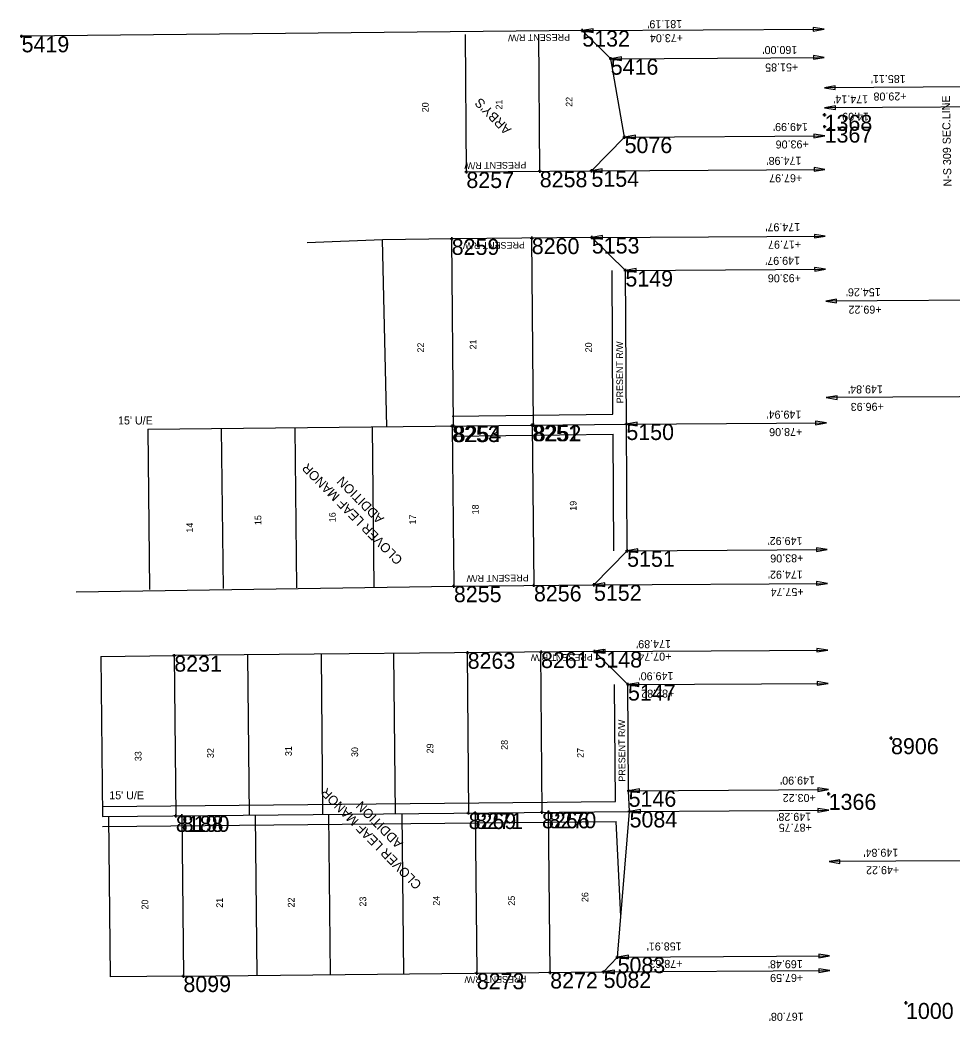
# Model space of a CAD drawing. Extents: x 2145146 to 2158053, y 137507 to 150829.
# Drawn here: x 2150207 to 2150906, y 144849 to 145599 of the extents above; entities that cross this region are included whole.
import ezdxf

# ---------------------------------------------------------------- set-up
doc = ezdxf.new("R2010")
doc.units = 0
for name, color, linetype in [('ALIGN_Cogo Points', 7, 'Continuous'), ('ALIGN_ROW Dimension', 7, 'Continuous'), ('ALIGN_ROW Line', 7, 'Continuous'), ('ALIGN_ROW Text', 7, 'Continuous'), ('PLSS_Block Line', 7, 'Continuous'), ('PLSS_Easement', 7, 'Continuous'), ('PLSS_Lot Line', 7, 'Continuous'), ('PLSS_Property Line', 7, 'Continuous'), ('PLSS_Text', 7, 'Continuous'), ('PLSS_Text_TURNED OFF', 7, 'Continuous')]:
    doc.layers.add(name, color=color, linetype=linetype)

# ---------------------------------------------------------------- blocks, each defined once
blk = doc.blocks.new('Arrowhd')
at = {"layer": 'PLSS_Property Line'}
blk.add_lwpolyline([(0.125, -0.021), (0.125, 0.021), (0, 0)], close=True, dxfattribs=at)

msp = doc.modelspace()

# ---------------------------------------------------------------- linework, layer by layer
at = {"layer": 'ALIGN_Cogo Points'}
for points in [[(2150207.75, 145586.84), (2150207.75, 145588.04), (2150207.75, 145586.84), (2150206.55, 145586.84), (2150207.75, 145586.84), (2150207.75, 145585.64), (2150207.75, 145586.84), (2150208.95, 145586.84)], [(2150627.9, 145591.12), (2150627.9, 145592.32), (2150627.9, 145591.12), (2150626.7, 145591.12), (2150627.9, 145591.12), (2150627.9, 145589.92), (2150627.9, 145591.12), (2150629.1, 145591.12)], [(2150649.21, 145570.05), (2150649.21, 145571.25), (2150649.21, 145570.05), (2150648.01, 145570.05), (2150649.21, 145570.05), (2150649.21, 145568.85), (2150649.21, 145570.05), (2150650.41, 145570.05)], [(2150809.47, 145528), (2150809.47, 145529.2), (2150809.47, 145528), (2150808.27, 145528), (2150809.47, 145528), (2150809.47, 145526.8), (2150809.47, 145528), (2150810.67, 145528)], [(2150809.52, 145519.17), (2150809.52, 145520.37), (2150809.52, 145519.17), (2150808.32, 145519.17), (2150809.52, 145519.17), (2150809.52, 145517.97), (2150809.52, 145519.17), (2150810.72, 145519.17)], [(2150659.58, 145511.33), (2150659.58, 145512.53), (2150659.58, 145511.33), (2150658.38, 145511.33), (2150659.58, 145511.33), (2150659.58, 145510.13), (2150659.58, 145511.33), (2150660.78, 145511.33)], [(2150541.04, 145485.16), (2150541.04, 145486.36), (2150541.04, 145485.16), (2150539.84, 145485.16), (2150541.04, 145485.16), (2150541.04, 145483.96), (2150541.04, 145485.16), (2150542.24, 145485.16)], [(2150596.04, 145485.7), (2150596.04, 145486.9), (2150596.04, 145485.7), (2150594.84, 145485.7), (2150596.04, 145485.7), (2150596.04, 145484.5), (2150596.04, 145485.7), (2150597.24, 145485.7)], [(2150634.74, 145486.08), (2150634.74, 145487.28), (2150634.74, 145486.08), (2150633.54, 145486.08), (2150634.74, 145486.08), (2150634.74, 145484.88), (2150634.74, 145486.08), (2150635.94, 145486.08)], [(2150530.05, 145435.05), (2150530.05, 145436.25), (2150530.05, 145435.05), (2150528.85, 145435.05), (2150530.05, 145435.05), (2150530.05, 145433.85), (2150530.05, 145435.05), (2150531.25, 145435.05)], [(2150590.05, 145435.64), (2150590.05, 145436.84), (2150590.05, 145435.64), (2150588.85, 145435.64), (2150590.05, 145435.64), (2150590.05, 145434.44), (2150590.05, 145435.64), (2150591.25, 145435.64)], [(2150635.05, 145436.08), (2150635.05, 145437.28), (2150635.05, 145436.08), (2150633.85, 145436.08), (2150635.05, 145436.08), (2150635.05, 145434.88), (2150635.05, 145436.08), (2150636.25, 145436.08)], [(2150660.2, 145411.33), (2150660.2, 145412.53), (2150660.2, 145411.33), (2150659, 145411.33), (2150660.2, 145411.33), (2150660.2, 145410.13), (2150660.2, 145411.33), (2150661.4, 145411.33)], [(2150530.37, 145294.83), (2150530.37, 145296.03), (2150530.37, 145294.83), (2150529.17, 145294.83), (2150530.37, 145294.83), (2150530.37, 145293.63), (2150530.37, 145294.83), (2150531.57, 145294.83)], [(2150531.45, 145294.84), (2150531.45, 145296.04), (2150531.45, 145294.84), (2150530.25, 145294.84), (2150531.45, 145294.84), (2150531.45, 145293.64), (2150531.45, 145294.84), (2150532.65, 145294.84)], [(2150590.37, 145295.41), (2150590.37, 145296.61), (2150590.37, 145295.41), (2150589.17, 145295.41), (2150590.37, 145295.41), (2150590.37, 145294.21), (2150590.37, 145295.41), (2150591.57, 145295.41)], [(2150591.45, 145295.42), (2150591.45, 145296.62), (2150591.45, 145295.42), (2150590.25, 145295.42), (2150591.45, 145295.42), (2150591.45, 145294.22), (2150591.45, 145295.42), (2150592.65, 145295.42)], [(2150660.92, 145296.33), (2150660.92, 145297.53), (2150660.92, 145296.33), (2150659.72, 145296.33), (2150660.92, 145296.33), (2150660.92, 145295.13), (2150660.92, 145296.33), (2150662.12, 145296.33)], [(2150661.51, 145201.33), (2150661.51, 145202.53), (2150661.51, 145201.33), (2150660.31, 145201.33), (2150661.51, 145201.33), (2150661.51, 145200.13), (2150661.51, 145201.33), (2150662.71, 145201.33)], [(2150531.67, 145174.83), (2150531.67, 145176.03), (2150531.67, 145174.83), (2150530.47, 145174.83), (2150531.67, 145174.83), (2150531.67, 145173.63), (2150531.67, 145174.83), (2150532.87, 145174.83)], [(2150591.67, 145175.42), (2150591.67, 145176.62), (2150591.67, 145175.42), (2150590.47, 145175.42), (2150591.67, 145175.42), (2150591.67, 145174.22), (2150591.67, 145175.42), (2150592.87, 145175.42)], [(2150636.66, 145175.86), (2150636.66, 145177.06), (2150636.66, 145175.86), (2150635.46, 145175.86), (2150636.66, 145175.86), (2150636.66, 145174.66), (2150636.66, 145175.86), (2150637.86, 145175.86)], [(2150322.13, 145122.78), (2150322.13, 145123.98), (2150322.13, 145122.78), (2150320.93, 145122.78), (2150322.13, 145122.78), (2150322.13, 145121.58), (2150322.13, 145122.78), (2150323.33, 145122.78)], [(2150541.99, 145124.93), (2150541.99, 145126.13), (2150541.99, 145124.93), (2150540.79, 145124.93), (2150541.99, 145124.93), (2150541.99, 145123.73), (2150541.99, 145124.93), (2150543.19, 145124.93)], [(2150596.99, 145125.47), (2150596.99, 145126.67), (2150596.99, 145125.47), (2150595.79, 145125.47), (2150596.99, 145125.47), (2150596.99, 145124.27), (2150596.99, 145125.47), (2150598.19, 145125.47)], [(2150636.99, 145125.86), (2150636.99, 145127.06), (2150636.99, 145125.86), (2150635.79, 145125.86), (2150636.99, 145125.86), (2150636.99, 145124.66), (2150636.99, 145125.86), (2150638.19, 145125.86)], [(2150662.13, 145101.09), (2150662.13, 145102.29), (2150662.13, 145101.09), (2150660.93, 145101.09), (2150662.13, 145101.09), (2150662.13, 145099.89), (2150662.13, 145101.09), (2150663.33, 145101.09)], [(2150859.27, 145060.92), (2150859.27, 145062.12), (2150859.27, 145060.92), (2150858.07, 145060.92), (2150859.27, 145060.92), (2150859.27, 145059.72), (2150859.27, 145060.92), (2150860.47, 145060.92)], [(2150662.61, 145021.5), (2150662.61, 145022.7), (2150662.61, 145021.5), (2150661.41, 145021.5), (2150662.61, 145021.5), (2150662.61, 145020.3), (2150662.61, 145021.5), (2150663.81, 145021.5)], [(2150812.52, 145019.18), (2150812.52, 145020.38), (2150812.52, 145019.18), (2150811.32, 145019.18), (2150812.52, 145019.18), (2150812.52, 145017.98), (2150812.52, 145019.18), (2150813.72, 145019.18)], [(2150323.31, 145002.7), (2150323.31, 145003.9), (2150323.31, 145002.7), (2150322.11, 145002.7), (2150323.31, 145002.7), (2150323.31, 145001.5), (2150323.31, 145002.7), (2150324.51, 145002.7)], [(2150327.82, 145002.74), (2150327.82, 145003.94), (2150327.82, 145002.74), (2150326.62, 145002.74), (2150327.82, 145002.74), (2150327.82, 145001.54), (2150327.82, 145002.74), (2150329.02, 145002.74)], [(2150542.69, 145004.85), (2150542.69, 145006.05), (2150542.69, 145004.85), (2150541.49, 145004.85), (2150542.69, 145004.85), (2150542.69, 145003.65), (2150542.69, 145004.85), (2150543.89, 145004.85)], [(2150547.69, 145004.9), (2150547.69, 145006.1), (2150547.69, 145004.9), (2150546.49, 145004.9), (2150547.69, 145004.9), (2150547.69, 145003.7), (2150547.69, 145004.9), (2150548.89, 145004.9)], [(2150597.69, 145005.39), (2150597.69, 145006.59), (2150597.69, 145005.39), (2150596.49, 145005.39), (2150597.69, 145005.39), (2150597.69, 145004.19), (2150597.69, 145005.39), (2150598.89, 145005.39)], [(2150602.69, 145005.43), (2150602.69, 145006.63), (2150602.69, 145005.43), (2150601.49, 145005.43), (2150602.69, 145005.43), (2150602.69, 145004.23), (2150602.69, 145005.43), (2150603.89, 145005.43)], [(2150663.32, 145006.03), (2150663.32, 145007.23), (2150663.32, 145006.03), (2150662.12, 145006.03), (2150663.32, 145006.03), (2150663.32, 145004.83), (2150663.32, 145006.03), (2150664.52, 145006.03)], [(2150654.34, 144896.86), (2150654.34, 144898.06), (2150654.34, 144896.86), (2150653.14, 144896.86), (2150654.34, 144896.86), (2150654.34, 144895.66), (2150654.34, 144896.86), (2150655.54, 144896.86)], [(2150328.99, 144882.66), (2150328.99, 144883.86), (2150328.99, 144882.66), (2150327.79, 144882.66), (2150328.99, 144882.66), (2150328.99, 144881.46), (2150328.99, 144882.66), (2150330.19, 144882.66)], [(2150548.85, 144884.82), (2150548.85, 144886.02), (2150548.85, 144884.82), (2150547.65, 144884.82), (2150548.85, 144884.82), (2150548.85, 144883.62), (2150548.85, 144884.82), (2150550.05, 144884.82)], [(2150603.85, 144885.36), (2150603.85, 144886.56), (2150603.85, 144885.36), (2150602.65, 144885.36), (2150603.85, 144885.36), (2150603.85, 144884.16), (2150603.85, 144885.36), (2150605.05, 144885.36)], [(2150643.85, 144885.75), (2150643.85, 144886.95), (2150643.85, 144885.75), (2150642.65, 144885.75), (2150643.85, 144885.75), (2150643.85, 144884.55), (2150643.85, 144885.75), (2150645.05, 144885.75)], [(2150870.47, 144862.54), (2150870.47, 144863.74), (2150870.47, 144862.54), (2150869.27, 144862.54), (2150870.47, 144862.54), (2150870.47, 144861.34), (2150870.47, 144862.54), (2150871.67, 144862.54)]]:
    msp.add_lwpolyline(points, dxfattribs=at)
at = {"layer": 'ALIGN_ROW Dimension'}
for points in [[(2150627.9, 145591.12), (2150809.08, 145592.21)], [(2150649.21, 145570.05), (2150809.21, 145571.01)], [(2150994.46, 145549.36), (2150809.35, 145548.25)], [(2150983.58, 145534.3), (2150809.44, 145533.25)], [(2150659.58, 145511.33), (2150809.56, 145512.23)], [(2150634.74, 145486.08), (2150809.71, 145487.13)], [(2150635.05, 145436.08), (2150810.01, 145437.13)], [(2150660.2, 145411.33), (2150810.16, 145412.23)], [(2150964.56, 145389.31), (2150810.31, 145388.39)], [(2150960.58, 145317), (2150810.74, 145316.1)], [(2150660.92, 145296.33), (2150810.85, 145297.23)], [(2150661.51, 145201.33), (2150811.43, 145202.23)], [(2150636.66, 145175.86), (2150811.58, 145176.91)], [(2150636.99, 145125.86), (2150811.88, 145126.91)], [(2150662.13, 145101.09), (2150812.03, 145101.99)], [(2150662.61, 145021.5), (2150812.51, 145022.4)], [(2150663.32, 145006.03), (2150812.6, 145006.93)], [(2150962.66, 144969.3), (2150812.83, 144968.4)], [(2150654.34, 144896.86), (2150813.25, 144897.81)], [(2150643.85, 144885.75), (2150813.32, 144886.77)]]:
    msp.add_lwpolyline(points, dxfattribs=at)
at = {"layer": 'ALIGN_ROW Line'}
for points in [[(2150541.04, 145485.16), (2150634.74, 145486.08), (2150659.58, 145511.33), (2150649.21, 145570.05), (2150627.9, 145591.12), (2150207.75, 145586.84)], [(2150531.67, 145174.83), (2150636.66, 145175.86), (2150661.51, 145201.33), (2150660.92, 145296.33), (2150660.2, 145411.33), (2150635.05, 145436.08), (2150530.05, 145435.05)], [(2150530.05, 145435.05), (2150478.3, 145434.29), (2150421.67, 145432.16)], [(2150328.99, 144882.66), (2150643.85, 144885.75), (2150654.34, 144896.86), (2150663.32, 145006.03), (2150662.61, 145021.5), (2150662.13, 145101.09), (2150636.99, 145125.86), (2150322.13, 145122.78)]]:
    msp.add_lwpolyline(points, dxfattribs=at)
at = {"layer": 'PLSS_Block Line'}
for points in [[(2150248.61, 145170.47), (2150531.74, 145174.87)], [(2150267.16, 145122.24), (2150322.13, 145122.78)], [(2150328.99, 144882.66), (2150274.02, 144882.13)]]:
    msp.add_lwpolyline(points, dxfattribs=at)
at = {"layer": 'PLSS_Easement'}
for points in [[(2150650.87, 145303.61), (2150650.2, 145411.27)], [(2150530.29, 145302.32), (2150650.87, 145303.61)], [(2150530.45, 145287.33), (2150650.96, 145288.61)], [(2150651.51, 145201.27), (2150650.96, 145288.61)], [(2150652.66, 145013.42), (2150652.13, 145101.03)], [(2150268.26, 145009.66), (2150652.66, 145013.42)], [(2150268.41, 144994.66), (2150653.29, 144998.43)], [(2150656.85, 144927.39), (2150653.29, 144998.43)]]:
    msp.add_lwpolyline(points, dxfattribs=at)
at = {"layer": 'PLSS_Lot Line'}
for points in [[(2150541.04, 145485.16), (2150540.39, 145588.2)], [(2150596.04, 145485.51), (2150595.39, 145588.54)], [(2150481.5, 145294.33), (2150478.3, 145434.29)], [(2150531.45, 145294.83), (2150530.05, 145435.05)], [(2150591.45, 145295.42), (2150590.15, 145435.63)], [(2150302.39, 145292.39), (2150660.96, 145296.22)], [(2150412.38, 145293.55), (2150413.68, 145173.56)], [(2150470.38, 145294.18), (2150471.67, 145174.18)], [(2150530.37, 145294.83), (2150531.67, 145174.83)], [(2150590.37, 145295.41), (2150591.67, 145175.42)], [(2150302.39, 145292.39), (2150303.68, 145172.37)], [(2150357.38, 145292.96), (2150358.68, 145172.96)], [(2150267.18, 145122.24), (2150268.33, 145002.16)], [(2150322.15, 145122.78), (2150323.31, 145002.7)], [(2150377.13, 145123.32), (2150378.28, 145003.24)], [(2150432.1, 145123.85), (2150433.26, 145003.78)], [(2150486.54, 145124.4), (2150487.7, 145004.32)], [(2150541.54, 145124.93), (2150542.69, 145004.85)], [(2150596.53, 145125.46), (2150597.69, 145005.39)], [(2150268.33, 145002.16), (2150663.15, 145006.03)], [(2150272.86, 145002.21), (2150274.02, 144882.13)], [(2150327.83, 145002.74), (2150328.99, 144882.66)], [(2150382.81, 145003.28), (2150383.97, 144883.2)], [(2150437.78, 145003.82), (2150438.94, 144883.74)], [(2150492.76, 145004.36), (2150493.92, 144884.28)], [(2150547.69, 145004.9), (2150548.85, 144884.82)], [(2150603.87, 144885.36), (2150602.69, 145005.39)]]:
    msp.add_lwpolyline(points, dxfattribs=at)

# ---------------------------------------------------------------- block references
at = {"layer": 'ALIGN_ROW Dimension'}
for p, xscale, yscale, rotation in [((2150809.08, 145592.21), 65.00000000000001, 64.99999999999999, -179.65177652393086), ((2150627.88, 145591.12), 65, 65, 0.2668843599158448), ((2150649.2, 145570.05), 65, 65, 0.2668843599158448), ((2150809.21, 145571.01), 65.00000000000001, 64.99999999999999, -179.65177652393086), ((2150809.33, 145548.25), 65, 65, 0.2668843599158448), ((2150809.42, 145533.25), 65, 65, 0.2668843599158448), ((2150659.57, 145511.33), 65, 65, 0.2668843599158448), ((2150809.56, 145512.23), 65.00000000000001, 64.99999999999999, -179.65177652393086), ((2150809.71, 145487.13), 65.00000000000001, 64.99999999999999, -179.65177652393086), ((2150634.72, 145486.08), 65, 65, 0.2668843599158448), ((2150635.03, 145436.09), 65, 65, 0.2668843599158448), ((2150810.01, 145437.13), 65.00000000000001, 64.99999999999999, -179.65177652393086), ((2150810.16, 145412.23), 65.00000000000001, 64.99999999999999, -179.65177652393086), ((2150660.19, 145411.33), 65, 65, 0.2668843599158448), ((2150810.29, 145388.39), 65, 65, 0.2668843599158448), ((2150810.73, 145316.1), 65, 65, 0.2668843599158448), ((2150660.9, 145296.33), 65, 65, 0.2668843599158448), ((2150810.85, 145297.23), 65.00000000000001, 64.99999999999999, -179.65177652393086), ((2150811.43, 145202.23), 65.00000000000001, 64.99999999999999, -179.65177652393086), ((2150661.49, 145201.33), 65, 65, 0.2668843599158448), ((2150636.65, 145175.86), 65, 65, 0.2668843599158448), ((2150811.58, 145176.91), 65.00000000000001, 64.99999999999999, -179.65177652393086), ((2150635.78, 145125.86), 65, 65, 0.2668843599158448), ((2150636.98, 145125.86), 65, 65, 0.2668843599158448), ((2150811.88, 145126.91), 65.00000000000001, 64.99999999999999, -179.65177652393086), ((2150662.12, 145101.09), 65, 65, 0.2668843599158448), ((2150812.03, 145101.99), 65.00000000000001, 64.99999999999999, -179.65177652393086), ((2150812.51, 145022.4), 65.00000000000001, 64.99999999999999, -179.65177652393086), ((2150662.59, 145021.5), 65, 65, 0.2668843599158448), ((2150663.3, 145006.03), 65, 65, 0.2668843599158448), ((2150812.6, 145006.93), 65.00000000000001, 64.99999999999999, -179.65177652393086), ((2150812.82, 144968.4), 65, 65, 0.2668843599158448), ((2150654.33, 144896.86), 65, 65, 0.2668843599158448), ((2150813.25, 144897.81), 65.00000000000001, 64.99999999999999, -179.65177652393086), ((2150643.83, 144885.75), 65, 65, 0.2668843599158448), ((2150813.32, 144886.77), 65.00000000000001, 64.99999999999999, -179.65177652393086)]:
    msp.add_blockref('Arrowhd', p, dxfattribs=dict(at, xscale=xscale, yscale=yscale, rotation=rotation))

# ---------------------------------------------------------------- texts
at = {"layer": 'ALIGN_Cogo Points'}
for s, p in [('5419', (2150207.75, 145574.84)), ('5132', (2150627.9, 145579.12)), ('5416', (2150649.21, 145558.05)), ('1368', (2150809.47, 145516)), ('1367', (2150809.52, 145507.17)), ('5076', (2150659.58, 145499.33)), ('8257', (2150541.04, 145473.16)), ('8258', (2150596.04, 145473.7)), ('5154', (2150634.74, 145474.08)), ('5153', (2150635.05, 145424.08)), ('8259', (2150530.05, 145423.05)), ('8260', (2150590.05, 145423.64)), ('5149', (2150660.2, 145399.33)), ('8253', (2150530.37, 145282.83)), ('8254', (2150531.45, 145282.84)), ('8251', (2150590.37, 145283.41)), ('8252', (2150591.45, 145283.42)), ('5150', (2150660.92, 145284.33)), ('5151', (2150661.51, 145189.33)), ('8255', (2150531.67, 145162.83)), ('8256', (2150591.67, 145163.42)), ('5152', (2150636.66, 145163.86)), ('8231', (2150322.13, 145110.78)), ('8263', (2150541.99, 145112.93)), ('8261', (2150596.99, 145113.47)), ('5148', (2150636.99, 145113.86)), ('5147', (2150662.13, 145089.09)), ('8906', (2150859.27, 145048.92)), ('5146', (2150662.61, 145009.5)), ('1366', (2150812.52, 145007.18)), ('8188', (2150323.31, 144990.7)), ('8190', (2150327.82, 144990.74)), ('8269', (2150542.69, 144992.85)), ('8271', (2150547.69, 144992.9)), ('8266', (2150597.69, 144993.39)), ('8270', (2150602.69, 144993.43)), ('5084', (2150663.32, 144994.03)), ('5083', (2150654.34, 144884.86)), ('8099', (2150328.99, 144870.66)), ('8273', (2150548.85, 144872.82)), ('8272', (2150603.85, 144873.36)), ('5082', (2150643.85, 144873.75)), ('1000', (2150870.47, 144850.54))]:
    msp.add_text(s, height=12, dxfattribs=at).set_placement(p)
at = {"layer": 'ALIGN_ROW Dimension'}
for s, p in [("181.19'", (2150702.71, 145598.99)), ('+73.04', (2150703.34, 145588.51)), ("160.00'", (2150789.02, 145579.64)), ('+51.85', (2150789.66, 145566.59)), ("185.11'", (2150870.23, 145557.88)), ("174.14'", (2150842.08, 145542.67)), ('+29.08', (2150870.87, 145544.82)), ('14.09', (2150842.72, 145529.62)), ("149.99'", (2150796.91, 145521.95)), ('+93.06', (2150797.55, 145508.9)), ("174.98'", (2150792.05, 145496.6)), ('+67.97', (2150792.69, 145483.54)), ("174.97'", (2150791.21, 145446.86)), ('+17.97', (2150791.85, 145433.81)), ("149.97'", (2150791.05, 145421.68)), ('+93.06', (2150791.7, 145408.63)), ("154.26'", (2150851.51, 145398.14)), ('+69.22', (2150852.15, 145385.09)), ("149.84'", (2150853.15, 145325.32)), ('+96.93', (2150853.8, 145312.27)), ("149.94'", (2150792.05, 145306.42)), ('+78.06', (2150792.7, 145293.37)), ("149.92'", (2150792.87, 145211.78)), ('+83.06', (2150793.52, 145198.73)), ("174.92'", (2150793.09, 145186.52)), ('+57.74', (2150793.73, 145173.47)), ("174.89'", (2150694.35, 145134.46)), ('+07.74', (2150694.63, 145125.05)), ("149.90'", (2150696.17, 145110.44)), ('+82.82', (2150696.81, 145097.39)), ("149.90'", (2150802.23, 145032.24)), ('+03.22', (2150802.87, 145019.19)), ("149.28'", (2150799.4, 145005.03)), ('+87.75', (2150799.84, 144996.92)), ("149.84'", (2150864.68, 144978.13)), ('+49.22', (2150865.32, 144965.08)), ("158.91'", (2150702.31, 144907.92)), ('+78.63', (2150702.95, 144894.87)), ("169.48'", (2150793.07, 144894.61)), ('+67.59', (2150793.41, 144884.33)), ("167.08'", (2150793.78, 144855.26))]:
    msp.add_text(s, height=6, rotation=180.3718, dxfattribs=at).set_placement(p)
at = {"layer": 'ALIGN_ROW Text'}
for rotation, p in [(180.58961, (2150618.67, 145588.61)), (180.58961, (2150585.91, 145492.85)), (180.58961, (2150584.84, 145432.9)), (90.34413, (2150658.56, 145311.82)), (180.58961, (2150587.64, 145183.51)), (180.58961, (2150635.67, 145124.13)), (90.22753, (2150660.14, 145028.38)), (180.58961, (2150585.98, 144882.89))]:
    msp.add_text('PRESENT R/W', height=5, rotation=rotation, dxfattribs=at).set_placement(p)
at = {"layer": 'PLSS_Text'}
for s, height, rotation, p in [('22', 5, 90, (2150620.54, 145534)), ('N-S 309 SEC.LINE', 6, 91.06379, (2150904.59, 145474.34)), ('20', 5, 90, (2150512.77, 145529.91)), ('21', 5, 90, (2150568.02, 145531.96)), ('22', 5, 90, (2150509.3, 145349.86)), ('21', 5, 90, (2150548.61, 145352.23)), ('20', 5, 90, (2150635.12, 145350.05)), ('18', 5, 90, (2150550.25, 145228.59)), ('19', 5, 90, (2150623.58, 145231.33)), ('15', 5, 90, (2150387.36, 145220.59)), ('16', 5, 90, (2150443.14, 145222.74)), ('17', 5, 90, (2150503.28, 145221.02)), ('14', 5, 90, (2150336.25, 145214.96)), ('31', 5, 90, (2150410.24, 145047.49)), ('30', 5, 90, (2150459.92, 145046.82)), ('29', 5, 90, (2150516.31, 145049.5)), ('28', 5, 90, (2150572.03, 145052.19)), ('33', 5, 90, (2150297.58, 145043.69)), ('32', 5, 90, (2150351.78, 145046.02)), ('27', 5, 90, (2150629.05, 145046.14)), ('21', 5, 90, (2150358.57, 144933.88)), ('22', 5, 90, (2150412.26, 144934.08)), ('23', 5, 90, (2150465.96, 144934.75)), ('24', 5, 90, (2150521.01, 144935.42)), ('25', 5, 90, (2150577.4, 144935.42)), ('26', 5, 90, (2150632.45, 144938.11)), ('20', 5, 90, (2150302.63, 144932.55))]:
    msp.add_text(s, height=height, rotation=rotation, dxfattribs=at).set_placement(p)
for p in [(2150280, 145295.98), (2150273.42, 145015.12)]:
    msp.add_text("15' U/E", height=6, dxfattribs=at).set_placement(p)
at = {"layer": 'PLSS_Text_TURNED OFF'}
for s, p in [("ARBY'S", (2150575.18, 145517.36)), ('CLOVER LEAF MANOR', (2150493.81, 145195.04)), ('ADDITION', (2150479.79, 145225.86)), ('CLOVER LEAF MANOR', (2150508.06, 144951.75)), ('ADDITION', (2150494.04, 144982.57))]:
    msp.add_text(s, height=7, rotation=134.65653, dxfattribs=at).set_placement(p)

doc.saveas('drawing.dxf')
